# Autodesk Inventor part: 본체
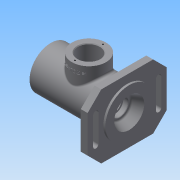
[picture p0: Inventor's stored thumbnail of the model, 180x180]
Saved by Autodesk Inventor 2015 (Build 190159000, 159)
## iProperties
Created: 2017-10
Part Number: 본체
Material: 일반
Document SubType Name: Modeling
Designer: user
Density: 1 g/cm^3
Appearance: 기본값
Mass: 273.395 g
Surface Area: 653.361 cm^2
Volume: 273.395 cm^3
Author: user
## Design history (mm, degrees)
sketch "스케치1"
  geometry: L1 (-57.5, 0)-(57.5, 0); L2 (-57.5, 0)-(-57.5, 31); L3 (-57.5, 31)-(-26.5, 31); L4 (23.5, 31)-(44.5, 31); L5 (44.5, 31)-(44.5, 47); L6 (44.5, 47)-(54.5, 47); L7 (54.5, 47)-(54.5, 35); L8 (54.5, 35)-(57.5, 35); L9 (57.5, 35)-(57.5, 0); L10 (-26.5, 31)-(23.5, 31); 2 further points
  constraints: 20 end point, 5 perpendicular, 2 coincident, 2 point on line, 1 collinear, 1 horizontal, 1 midpoint, 1 vertical
  dimensions: "d0" = 115 distance of L1.start L1.end; "d1" = 31 distance of L1.start L2.end; "d7" = 10 distance of L5.end L6.end; "d9" = 3 distance of L7.end L8.end; "d19" = 35 distance of L8.end L1.end; "d37" = 16 distance of L4.end L5.end
revolve "회전1" sketch "스케치1" stored, may be unused: angle "d10" = 90 deg
sketch "스케치2"
  geometry: L1 (-58, -47)-(58, -47); L2 (58, -47)-(58, 47); L3 (58, 47)-(-58, 47); L4 (-58, 47)-(-58, -47); L5 (-58, -47)-(58, 47); L6 (58, -47)-(-58, 47); C1 r 47 at (0, 0) reference
  constraints: 12 end point, 2 parallel, 1 horizontal, 1 perpendicular
  dimensions: "d12" = 116 distance of L3.end L2.end; "d13" = 94 distance of L2.end L1.end
extrude "돌출1" join sketch "스케치2" distance "d14" = 10; taper "d15" = 0 deg
chamfer "모따기1" distance "d16" = 20; stored, may be unused: second distance "d17" = 2, angle "d18" = 45 deg
sketch "스케치3"
  geometry: L1 (-104, 7)-(-104, 47); L2 (-12, 47)-(-12, 7); L3 (-104, 47)-(-104, 7); L4 (-108, 47)-(-108, 7); L5 (-100, 7)-(-100, 47); L6 (-12, 47)-(-12, 7); L7 (-16, 47)-(-16, 7); L8 (-8, 7)-(-8, 47); A1 r 4 centre (-104, 47) between (-100, 47) and (-108, 47); A2 r 4 centre (-104, 7) between (-108, 7) and (-100, 7); A3 r 4 centre (-12, 47) between (-8, 47) and (-16, 47); A4 r 4 centre (-12, 7) between (-16, 7) and (-8, 7); 2 further points
  constraints: 20 end point, 8 point on circle, 8 tangent, 4 centre point, 4 equal length, 2 midpoint
  dimensions: "d22" = 40 distance of L1.start L1.end; "d23" = 92 distance of L1.end L2.start; "d24" = 40 distance of L2.start L2.end; "d25" = 8 diameter of A2; "d26" = 8 diameter of A4
extrude "돌출2" cut sketch "스케치3" distance "d27" = 13; taper "d28" = 0 deg
sketch "스케치4"
  geometry: C1 r 31 at (0, 0) reference
hole "구멍1" sketch "스케치4" at (0, 0) diameter "d29" = 40.376; stored, may be unused: countersink angle "d33" = 90 deg, drill point angle "d35" = 118 deg; dims "d30" = 9, "d31" = 4, "d32" = 2, "d34" = 12
sketch "스케치5"
  geometry: L1 (57.5, -35)-(57.5, 35) reference; L2 (57.5, 0)-(57.5, 22); L3 (43.5, 16)-(57.5, 22); L4 (43.5, 16)-(43.5, 12.904); L5 (36.2, 10)-(36.2, 12.5); L6 (36.2, 12.5)-(42.8, 12.5); L7 (36.2, 12.5)-(36.2, 10); L8 (36.2, 10)-(33.5, 10); L9 (33.5, 10)-(33.5, 16.5); L10 (33.5, 16.5)-(28.5, 16.5); L11 (28.5, 16.5)-(28.5, 17.5); L12 (28.5, 17.5)-(17.5, 17.5); L13 (17.5, 17.5)-(17.5, 26); L14 (17.5, 26)-(-20.5, 26); L15 (-20.5, 26)-(-20.5, 17.5); L16 (-20.5, 17.5)-(-31.5, 17.5); L17 (-31.5, 17.5)-(-31.5, 18.5); L18 (-31.5, 18.5)-(-33.25, 18.5); L19 (-33.25, 18.5)-(-33.25, 17.5); L20 (-33.25, 17.5)-(-36.5, 17.5); L21 (-36.5, 17.5)-(-36.5, 20); L22 (-36.5, 20)-(-45.5, 20); L23 (-48.5, 0)-(57.5, 0); L24 (-45.5, 20)-(-45.5, 24); L25 (-45.5, 24)-(-48.5, 24); L26 (-48.5, 24)-(-48.5, 0); L27 (42.8, 12.5)-(43.5, 12.904); 2 further points
  constraints: 52 end point, 14 perpendicular, 6 point on line, 1 horizontal, 1 midpoint
  dimensions: "d38" = 22 distance of L2.start L2.end; "d45" = 2.5 distance of L5.start L5.end; "d46" = 2.7 distance of L5.start L8.end; "d47" = 6.5 distance of L8.end L9.end; "d48" = 5 distance of L9.end L10.end; "d49" = 1 distance of L10.end L11.end; "d50" = 11 distance of L11.end L12.end; "d51" = 8.5 distance of L12.end L13.end; "d52" = 38 distance of L13.end L14.end; "d53" = 8.5 distance of L14.end L15.end; "d54" = 11 distance of L15.end L16.end; "d55" = 1 distance of L16.end L17.end; "d56" = 1.75 distance of L17.end L18.end; "d57" = 1 distance of L18.end L19.end (derived); "d58" = 3.25 distance of L19.end L20.end; "d59" = 2.5 distance of L20.end L21.end; "d60" = 9 distance of L21.end L22.end; "d88" = 4 distance of L22.end L24.end; "d89" = 3 distance of L24.end L25.end; "d92" = 30 deg angle of L6 L27
revolve "회전2" sketch "스케치5" stored, may be unused: angle "d61" = 90 deg
node "작업 평면1"
sketch "스케치6"
  geometry: L1 (57.5, 31)-(57.5, -31) reference; L2 (57.5, 0)-(1.5, 0); C1 r 25 at (1.5, 0); 1 further point
  constraints: 2 end point, 1 centre point, 1 coincident, 1 horizontal, 1 midpoint
  dimensions: "d63" = 56 distance of L2.start L2.end; "d64" = 50 diameter of C1
extrude "돌출3" join sketch "스케치6" stored distance "d65" = 13; taper "d66" = 0 deg
sketch "스케치7"
  geometry: C1 r 25 at (0, 0) reference; C2 r 16 at (0, 0)
  constraints: 1 centre point, 1 coincident
  dimensions: "d67" = 32 diameter of C2
extrude "돌출4" cut sketch "스케치7" stored distance "d68" = 13; taper "d69" = 0 deg
sketch "스케치8"
  geometry: 2 further points
hole "구멍2" sketch "스케치8" at (0, 20.5), (0, -20.5) diameter "d71" = 2.459; stored, may be unused: countersink angle "d75" = 90 deg, drill point angle "d77" = 118 deg; dims "d72" = 6, "d73" = 4, "d74" = 2, "d76" = 8
chamfer "모따기2" distance "d78" = 1; stored, may be unused: second distance "d79" = 2, angle "d80" = 45 deg
fillet "모깎기1" dims "d81" = 0.3
fillet "모깎기2" dims "d82" = 3
node "작업 평면2"
sketch "스케치9"
  geometry: L1 (-57.5, -31)-(-57.5, 31) reference; L2 (-26.5, 47)-(23.5, 47) reference; 2 further points
  constraints: 1 other
  dimensions: "d84" = 56 horizontal distance of L1.end point (-1.5, 37); "d85" = 10 distance from line of point (-1.5, 37) L2
feature "엠보싱1" sketch "스케치9" dims "d0" = 115, "d1" = 31, "d7" = 10, "d9" = 3, "d19" = 35, "d37" = 16, "d86" = 0.5, "d87" = 0
node "솔리드1"
other parameters: "d62" = 47, "d83" = 31
